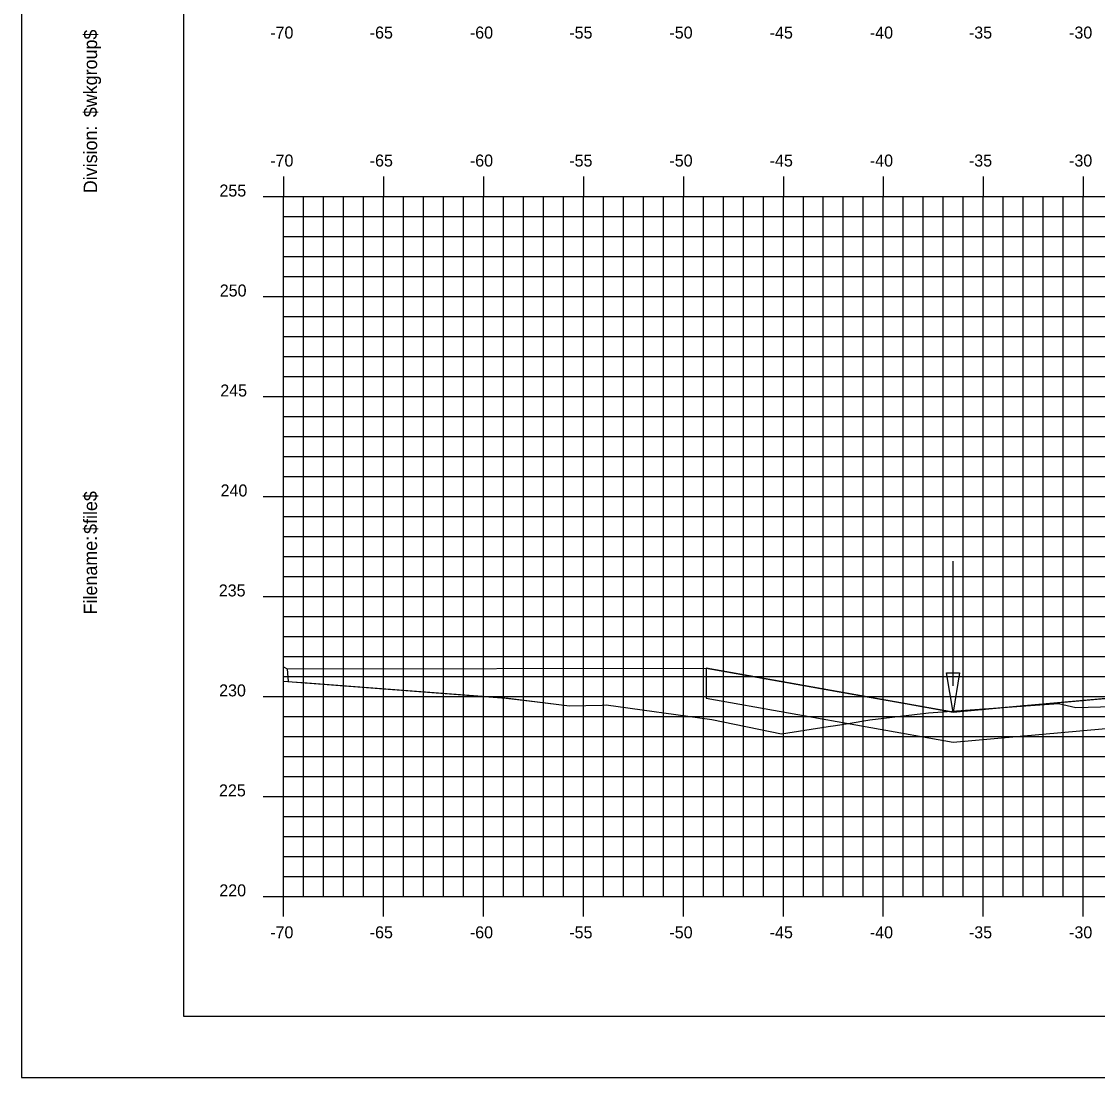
# Model space of a CAD drawing. Extents: x -22 to 1480, y -1511 to 8.
# Drawn here: x 770.3 to 824.1, y -1511.4 to -1458.6 of the extents above; entities that cross this region are included whole.
import ezdxf

# ---------------------------------------------------------------- set-up
doc = ezdxf.new("R2010")
doc.units = 0
for name, color, linetype in [('BORDER', 7, 'Continuous'), ('D_Drainage_Ditch_Line', 7, 'Continuous'), ('D_Roadway_Centerline', 7, 'Continuous'), ('D_Roadway_SlopeLines', 7, 'Continuous'), ('H_V ANNOTATION', 7, 'Continuous'), ('MAJOR', 7, 'Continuous'), ('MINOR', 7, 'Continuous'), ('PLOT BOUNDARY', 7, 'Continuous'), ('S_Roadway_Centerline', 7, 'Continuous')]:
    doc.layers.add(name, color=color, linetype=linetype)

msp = doc.modelspace()

# ---------------------------------------------------------------- linework, layer by layer
at = {"layer": 'BORDER'}
for p, q in [((778.426, -1403.331), (778.426, -1508.331)), ((778.426, -1508.331), (938.426, -1508.331))]:
    msp.add_line(p, q, dxfattribs=at)
at = {"layer": 'D_Drainage_Ditch_Line'}
msp.add_line((816.911, -1491.803), (816.911, -1485.56), dxfattribs=at)
msp.add_lwpolyline([(816.583, -1491.147), (817.239, -1491.147), (816.911, -1493.115)], close=True, dxfattribs=at)
at = {"layer": 'D_Roadway_Centerline'}
msp.add_lwpolyline([(783.608, -1490.947), (804.561, -1490.914), (809.069, -1491.719), (812.437, -1492.321), (814.337, -1492.66), (816.911, -1493.115), (819.605, -1492.872), (820.973, -1492.75), (824.873, -1492.402)], dxfattribs=at)
at = {"layer": 'D_Roadway_SlopeLines'}
msp.add_lwpolyline([(833.12, -1491.665), (816.911, -1493.115), (804.561, -1490.914), (804.561, -1492.414), (816.911, -1494.615), (833.12, -1493.165)], close=True, dxfattribs=at)
for points in [[(816.911, -1493.115), (804.561, -1490.914)], [(816.911, -1493.115), (804.561, -1490.914)], [(833.12, -1491.665), (816.911, -1493.115)], [(833.12, -1491.665), (816.911, -1493.115)]]:
    msp.add_lwpolyline(points, dxfattribs=at)
at = {"layer": 'MAJOR'}
for p, q in [((783.426, -1466.329), (783.426, -1467.331)), ((788.426, -1466.329), (788.426, -1467.331)), ((793.426, -1466.329), (793.426, -1467.331)), ((798.426, -1466.329), (798.426, -1467.331)), ((803.426, -1466.329), (803.426, -1467.331)), ((808.426, -1466.329), (808.426, -1467.331)), ((813.426, -1466.329), (813.426, -1467.331)), ((818.426, -1466.329), (818.426, -1467.331)), ((823.426, -1466.329), (823.426, -1467.331)), ((782.424, -1467.331), (783.426, -1467.331)), ((783.426, -1467.331), (923.426, -1467.331)), ((783.426, -1502.331), (783.426, -1467.331)), ((783.426, -1502.331), (783.426, -1467.331)), ((783.426, -1467.331), (923.426, -1467.331)), ((788.426, -1502.331), (788.426, -1467.331)), ((793.426, -1502.331), (793.426, -1467.331)), ((798.426, -1502.331), (798.426, -1467.331)), ((803.426, -1502.331), (803.426, -1467.331)), ((808.426, -1502.331), (808.426, -1467.331)), ((813.426, -1502.331), (813.426, -1467.331)), ((818.426, -1502.331), (818.426, -1467.331)), ((823.426, -1502.331), (823.426, -1467.331)), ((782.424, -1472.331), (783.426, -1472.331)), ((783.426, -1472.331), (923.426, -1472.331)), ((782.424, -1477.331), (783.426, -1477.331)), ((783.426, -1477.331), (923.426, -1477.331)), ((782.424, -1482.331), (783.426, -1482.331)), ((783.426, -1482.331), (923.426, -1482.331)), ((782.424, -1487.331), (783.426, -1487.331)), ((783.426, -1487.331), (923.426, -1487.331)), ((782.424, -1492.331), (783.426, -1492.331)), ((783.426, -1492.331), (923.426, -1492.331)), ((782.424, -1497.331), (783.426, -1497.331)), ((783.426, -1497.331), (923.426, -1497.331)), ((782.424, -1502.331), (783.426, -1502.331)), ((783.426, -1502.331), (923.426, -1502.331)), ((783.426, -1502.331), (923.426, -1502.331)), ((783.426, -1503.333), (783.426, -1502.331)), ((788.426, -1503.333), (788.426, -1502.331)), ((793.426, -1503.333), (793.426, -1502.331)), ((798.426, -1503.333), (798.426, -1502.331)), ((803.426, -1503.333), (803.426, -1502.331)), ((808.426, -1503.333), (808.426, -1502.331)), ((813.426, -1503.333), (813.426, -1502.331)), ((818.426, -1503.333), (818.426, -1502.331)), ((823.426, -1503.333), (823.426, -1502.331))]:
    msp.add_line(p, q, dxfattribs=at)
at = {"layer": 'MINOR'}
for p, q in [((784.426, -1502.331), (784.426, -1467.331)), ((785.426, -1502.331), (785.426, -1467.331)), ((786.426, -1502.331), (786.426, -1467.331)), ((787.426, -1502.331), (787.426, -1467.331)), ((789.426, -1502.331), (789.426, -1467.331)), ((790.426, -1502.331), (790.426, -1467.331)), ((791.426, -1502.331), (791.426, -1467.331)), ((792.426, -1502.331), (792.426, -1467.331)), ((794.426, -1502.331), (794.426, -1467.331)), ((795.426, -1502.331), (795.426, -1467.331)), ((796.426, -1502.331), (796.426, -1467.331)), ((797.426, -1502.331), (797.426, -1467.331)), ((799.426, -1502.331), (799.426, -1467.331)), ((800.426, -1502.331), (800.426, -1467.331)), ((801.426, -1502.331), (801.426, -1467.331)), ((802.426, -1502.331), (802.426, -1467.331)), ((804.426, -1502.331), (804.426, -1467.331)), ((805.426, -1502.331), (805.426, -1467.331)), ((806.426, -1502.331), (806.426, -1467.331)), ((807.426, -1502.331), (807.426, -1467.331)), ((809.426, -1502.331), (809.426, -1467.331)), ((810.426, -1502.331), (810.426, -1467.331)), ((811.426, -1502.331), (811.426, -1467.331)), ((812.426, -1502.331), (812.426, -1467.331)), ((814.426, -1502.331), (814.426, -1467.331)), ((815.426, -1502.331), (815.426, -1467.331)), ((816.426, -1502.331), (816.426, -1467.331)), ((817.426, -1502.331), (817.426, -1467.331)), ((819.426, -1502.331), (819.426, -1467.331)), ((820.426, -1502.331), (820.426, -1467.331)), ((821.426, -1502.331), (821.426, -1467.331)), ((822.426, -1502.331), (822.426, -1467.331)), ((783.426, -1468.331), (923.426, -1468.331)), ((783.426, -1468.331), (784.428, -1468.331)), ((783.426, -1469.331), (923.426, -1469.331)), ((783.426, -1469.331), (784.428, -1469.331)), ((783.426, -1470.331), (923.426, -1470.331)), ((783.426, -1470.331), (784.428, -1470.331)), ((783.426, -1471.331), (923.426, -1471.331)), ((783.426, -1471.331), (784.428, -1471.331)), ((783.426, -1473.331), (923.426, -1473.331)), ((783.426, -1473.331), (784.428, -1473.331)), ((783.426, -1474.331), (923.426, -1474.331)), ((783.426, -1474.331), (784.428, -1474.331)), ((783.426, -1475.331), (923.426, -1475.331)), ((783.426, -1475.331), (784.428, -1475.331)), ((783.426, -1476.331), (923.426, -1476.331)), ((783.426, -1476.331), (784.428, -1476.331)), ((783.426, -1478.331), (923.426, -1478.331)), ((783.426, -1478.331), (784.428, -1478.331)), ((783.426, -1479.331), (923.426, -1479.331)), ((783.426, -1479.331), (784.428, -1479.331)), ((783.426, -1480.331), (923.426, -1480.331)), ((783.426, -1480.331), (784.428, -1480.331)), ((783.426, -1481.331), (923.426, -1481.331)), ((783.426, -1481.331), (784.428, -1481.331)), ((783.426, -1483.331), (923.426, -1483.331)), ((783.426, -1483.331), (784.428, -1483.331)), ((783.426, -1484.331), (923.426, -1484.331)), ((783.426, -1484.331), (784.428, -1484.331)), ((783.426, -1485.331), (923.426, -1485.331)), ((783.426, -1485.331), (784.428, -1485.331)), ((783.426, -1486.331), (923.426, -1486.331)), ((783.426, -1486.331), (784.428, -1486.331)), ((783.426, -1488.331), (923.426, -1488.331)), ((783.426, -1488.331), (784.428, -1488.331)), ((783.426, -1489.331), (923.426, -1489.331)), ((783.426, -1489.331), (784.428, -1489.331)), ((783.426, -1490.331), (923.426, -1490.331)), ((783.426, -1490.331), (784.428, -1490.331)), ((783.426, -1491.331), (923.426, -1491.331)), ((783.426, -1491.331), (784.428, -1491.331)), ((783.426, -1493.331), (923.426, -1493.331)), ((783.426, -1493.331), (784.428, -1493.331)), ((783.426, -1494.331), (923.426, -1494.331)), ((783.426, -1494.331), (784.428, -1494.331)), ((783.426, -1495.331), (923.426, -1495.331)), ((783.426, -1495.331), (784.428, -1495.331)), ((783.426, -1496.331), (923.426, -1496.331)), ((783.426, -1496.331), (784.428, -1496.331)), ((783.426, -1498.331), (923.426, -1498.331)), ((783.426, -1498.331), (784.428, -1498.331)), ((783.426, -1499.331), (923.426, -1499.331)), ((783.426, -1499.331), (784.428, -1499.331)), ((783.426, -1500.331), (923.426, -1500.331)), ((783.426, -1500.331), (784.428, -1500.331)), ((783.426, -1501.331), (923.426, -1501.331)), ((783.426, -1501.331), (784.428, -1501.331))]:
    msp.add_line(p, q, dxfattribs=at)
at = {"layer": 'PLOT BOUNDARY'}
msp.add_lwpolyline([(770.333, -1511.39), (940.333, -1511.39), (940.333, -1401.39), (770.333, -1401.39)], close=True, dxfattribs=at)
at = {"layer": 'S_Roadway_Centerline'}
for points in [[(783.426, -1490.856), (783.608, -1490.947), (783.638, -1491.166), (783.658, -1491.578), (783.869, -1491.595), (784.622, -1491.652), (794.475, -1492.407), (794.482, -1492.407), (794.495, -1492.407), (794.569, -1492.414), (794.643, -1492.423), (794.669, -1492.426), (797.726, -1492.804), (799.36, -1492.771), (799.574, -1492.754), (804.845, -1493.483), (808.34, -1494.195), (810.669, -1493.838), (811.032, -1493.786), (811.665, -1493.684), (812.753, -1493.508), (815.689, -1493.154), (822.183, -1492.685), (823.058, -1492.887), (824.903, -1492.832)], [(783.426, -1491.561), (794.569, -1492.414), (796.112, -1492.606), (797.726, -1492.804), (799.36, -1492.771), (799.574, -1492.754), (804.845, -1493.483), (808.34, -1494.195), (810.669, -1493.838), (811.032, -1493.786), (811.665, -1493.684), (812.753, -1493.508), (815.689, -1493.154), (822.183, -1492.685), (823.058, -1492.887), (824.903, -1492.832)]]:
    msp.add_lwpolyline(points, dxfattribs=at)

# ---------------------------------------------------------------- texts
at = {"layer": 'BORDER'}
for s, p in [('$wkgroup$', (774.111, -1463.362)), ('Division:', (774.111, -1467.165)), ('$file$', (774.111, -1484.206)), ('Filename:', (774.111, -1488.233))]:
    msp.add_text(s, height=0.6696, rotation=90, dxfattribs=at).set_placement(p)
at = {"layer": 'H_V ANNOTATION'}
for s, p in [('-70', (782.768, -1459.431)), ('-65', (787.744, -1459.431)), ('-60', (792.752, -1459.431)), ('-55', (797.722, -1459.431)), ('-50', (802.73, -1459.431)), ('-45', (807.744, -1459.431)), ('-40', (812.752, -1459.431)), ('-35', (817.706, -1459.431)), ('-30', (822.714, -1459.431)), ('-70', (782.768, -1465.831)), ('-65', (787.744, -1465.831)), ('-60', (792.752, -1465.831)), ('-55', (797.722, -1465.831)), ('-50', (802.73, -1465.831)), ('-45', (807.744, -1465.831)), ('-40', (812.752, -1465.831)), ('-35', (817.706, -1465.831)), ('-30', (822.714, -1465.831)), ('255', (780.229, -1467.331)), ('250', (780.245, -1472.331)), ('245', (780.272, -1477.331)), ('240', (780.288, -1482.331)), ('235', (780.197, -1487.331)), ('230', (780.213, -1492.331)), ('225', (780.208, -1497.331)), ('220', (780.224, -1502.331)), ('-70', (782.768, -1504.431)), ('-65', (787.744, -1504.431)), ('-60', (792.752, -1504.431)), ('-55', (797.722, -1504.431)), ('-50', (802.73, -1504.431)), ('-45', (807.744, -1504.431)), ('-40', (812.752, -1504.431)), ('-35', (817.706, -1504.431)), ('-30', (822.714, -1504.431))]:
    msp.add_text(s, height=0.6, dxfattribs=at).set_placement(p)

doc.saveas('drawing.dxf')
